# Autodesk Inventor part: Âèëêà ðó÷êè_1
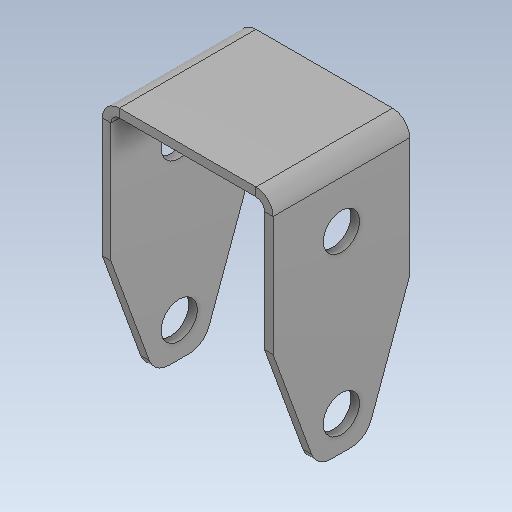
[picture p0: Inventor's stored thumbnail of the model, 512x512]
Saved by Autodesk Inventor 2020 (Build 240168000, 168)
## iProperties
Created: 1900-01
Part Number: Âèëêà ðó÷êè_1
Material: Générique
Document SubType Name: Modeling
Designer: bruno
Density: 1 g/cm^3
Appearance: Par défaut
Author: bruno
Revision Number: ANYUNSPECIFIED
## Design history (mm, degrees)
feature "Base1"
node "Solide1"
